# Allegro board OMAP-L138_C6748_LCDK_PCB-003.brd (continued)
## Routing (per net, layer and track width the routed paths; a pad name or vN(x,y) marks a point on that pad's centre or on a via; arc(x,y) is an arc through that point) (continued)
VCC_5VD: length 315.3
  TOP w0.254: 25.15,49.53 25.15,49.53 U16.7 ; U3.4 30.73,74.93 v1(30.48,75.18) 30.23,74.93 U3.5 ; U3.9 v1(26.92,72.87) ; 24.89,49.53 24.65,49.77 U15.1 ; U3.28 v1(33.78,70.87) ; U3.15 v1(26.92,69.87)
  TOP w0.457: v1(30.23,64.26) R13.2 R10.2 R11.2 ; v1(23.37,39.37) 23.69,39.69 DN2.2 ; 24.89,49.53 v1(26.67,49.53) ; v1(32.77,67.06) 33.27,66.55 C7.1 ; DN1.2 21.27,39.69 v1(21.59,39.37)
  LYR3 w0.457: v1(86.36,43.69) 87.12,43.69 88.73,42.08 100.58,42.08 ; 20.57,72.64 7.37,72.64 TP3.1
  LYR3 w1.016: J5.1 67.87,2.74 69.6,1.02 99.57,1.02 100.58,2.03 100.58,89.15 99.57,90.17 73.91,90.17 71.63,87.88 55.88,87.88 53.34,85.34 41.91,85.34 40.13,83.57 40.13,82.8
  LYR4 w0.762: v1(26.67,49.53) 27.94,49.53 ; 27.94,49.53 27.94,61.21 30.23,63.5 v1(30.23,64.26) v1(31.24,64.26) ; 27.94,49.53 27.94,43.94 v1(23.37,39.37) v1(21.59,39.37)
  BOTTOM w0.381: U5.7 v1(22.28,80.72) ; U5.6 v1(22.93,80.72) ; U5.8 v1(21.63,80.72)
  BOTTOM w0.457: 25.91,49.53 25.4,49.53 24.89,50.04 C104.1 ; 25.91,49.53 v1(26.67,49.53) ; 25.91,49.53 C141.1 ; U4.7 34.29,85.09 v1(36.32,83.06) 36.68,82.7 U6.5 ; R26.2 R23.2 v1(20.57,70.36) ; R3.1 33.27,70.36 v1(33.78,70.87) ; R9.1 5.84,76.71 5.59,76.45 5.59,74.42 TP3.1 ; R211.1 v1(86.36,43.69) 86.36,43.94 85.85,44.45 82.8,44.45 82.3,43.94 R210.1 ; v1(20.57,66.55) R22.2 R24.2 ; v1(26.92,69.87) 25.1,69.87 C8.1 ; C18.1 29.97,66.04 30.23,65.79 R13.2 R15.1 v1(31.24,64.26) ; C9.1 25.11,72.87 v1(26.92,72.87) ; C10.1 v1(30.48,75.18) ; U4.14 v1(29.21,80.39) ; R12.2 v1(32.77,74.68) ; v1(21.59,39.37) R121.1 R120.1
VCC_5VD_IN: length 57.9
  TOP w0.305: U2.5 v1(12.95,76.2) ; U2.4 12.18,75.7 12.45,75.44 v1(12.95,75.44)
  TOP w0.457: v1(12.95,73.91) C2.1 14.29,74.68 ; v1(12.95,73.91) C3.1 ; v1(12.95,73.91) v1(12.95,74.68) ; v1(12.95,75.44) v1(12.95,76.2) C1.1 14.29,75.44 ; v1(12.95,75.44) v1(12.95,74.68) ; v1(12.95,75.44) 14.29,75.44 ; 14.29,74.68 v1(12.95,74.68) ; 14.29,74.68 14.29,75.44
  LYR3 w0.762: 22.28,86.49 20.95,85.16 20.95,84.45 TP1.1 17.27,80.77 17.27,78.49 14.99,76.2 v1(12.95,76.2) v1(12.95,75.44) v1(12.95,74.68) v1(12.95,73.91) ; 22.28,86.49 31.88,86.49 ; 22.28,86.49 v1(22.28,87.38) ; 31.88,86.49 v1(33.02,87.63) ; 31.88,86.49 31.88,83.69 v1(30.99,82.8)
  BOTTOM w0.381: U5.2 v1(22.28,87.38) 22.73,87.38 22.93,87.18 U5.3
  BOTTOM w0.457: U4.13 30.48,82.3 v1(30.99,82.8) ; U4.8 35.56,87.38 35.31,87.63 v1(33.02,87.63) 33.02,87.88 32.51,88.39 R21.1
VCC_AIC3106_3V3A: length 3.8
  BOTTOM w0.457: C183.1 v1(18.8,25.65) ; v1(18.8,25.65) C182.1 ; v1(18.8,25.65) v1(18.8,24.89)
VCC_AIC3106_3V3D: length 31.9
  TOP w0.254: 14.49,24.14 v1(14.48,24.13) ; U22.24 17.99,24.98 v1(17.91,24.89) ; v1(13.97,34.29) 14.49,33.77 U22.44
  TOP w0.457: C190.1 v1(13.97,34.29) ; v1(17.91,24.89) v1(17.14,24.13)
  BOTTOM w0.457: 13.46,24.89 C187.1 12.7,25.65 11.94,26.42 11.94,32.26 v1(13.97,34.29) ; 13.46,24.89 v1(13.46,24.13) ; 13.46,24.89 14.48,24.89 ; v1(14.48,24.13) 14.48,23.37 ; v1(14.48,24.13) v1(13.46,24.13) ; v1(14.48,24.13) 14.48,24.89 ; 14.48,23.37 13.46,23.37 ; 14.48,23.37 C188.1 C189.1 13.46,23.37 ; v1(13.46,24.13) 13.46,23.37 ; 17.14,24.89 14.48,24.89 ; 17.14,24.89 v1(17.91,24.89) 17.91,23.43 FB16.1 17.14,23.43 v1(17.14,24.13) 17.14,24.89
VCC_USB0_IN: length 11.7
  TOP w0.457: v1(36.32,84.33) 36.83,84.84 R54.2 ; v1(33.02,84.33) 32.77,84.58 J2.1
  LYR4 w0.457: v1(33.02,84.33) v1(36.32,84.33)
  BOTTOM w0.457: U4.6 v1(33.02,84.33) 34.29,83.06 U4.10
VCC_USB0_IN_K: length 16.7
  BOTTOM w0.381: U5.4 25.19,86.07
  BOTTOM w0.457: 29.21,85.09 U4.3 R25.1 C19.1 ; 29.21,85.09 26.16,85.09 25.19,86.07 ; 29.21,85.09 30.73,85.09 33.02,82.8 U4.11
VDD_ALIVE: length 12
  TOP w0.121: U3.12 27.17,71.37 v1(26.92,71.12) 26.42,71.12 25.53,70.23 25.53,69.72 25.15,69.34 C15.1
  LYR4 w0.133: v1(26.92,71.12) 26.16,70.36 26.16,68.07 25.65,67.56 24.38,67.56 TP8.1
ACTIVITYLED: length 33.6
  TOP w0.121: v1(72.64,73.66) 72.14,73.15 72.14,72.14 72.4,71.87 U23.3
  LYR3 w0.133: v1(72.64,73.66) 72.14,73.15 72.14,72.13 72.64,71.63 96.27,71.63 v1(96.77,71.12)
  BOTTOM w0.121: R188.1 72.39,74.93 72.64,74.68 v1(72.64,73.66) ; R181.1 v1(96.77,71.12)
AES_ADDR/FS: length 2.7
  TOP w0.121: U26.D5 v1(9.91,8.62)
  BOTTOM w0.121: v1(9.91,8.62) 8.87,9.65 R205.2
AES_CLK: length 5
  TOP w0.121: R200.2 R201.2 13.97,12.19 13.7,11.92 U26.E2
AES_DATA: length 4.9
  TOP w0.121: R204.2 R202.2 U26.E3
AIC_BCLK: length 123.5
  TOP w0.121: v1(18.54,35.81) 18.54,34.29 17.49,33.24 U22.38
  LYR3 w0.133: v1(72.64,47.75) 69.34,51.05 34.92,51.05 34.29,50.42 31.88,50.42 28.96,47.5 28.96,40.77 25.53,37.34 23.75,37.34 22.23,35.81 v1(18.54,35.81) ; v1(71.76,45.7) 84.86,45.7 85.28,45.28 85.93,45.28 v1(86.36,45.7)
  BOTTOM w0.121: v1(72.64,47.75) 72.64,46.58 v1(71.76,45.7) R95.2 ; J15.41 97.16,19.05 97.16,23.5 96.52,24.13 95.25,24.13 94.74,24.64 94.74,30.73 93.98,31.5 93.98,38.86 93.22,39.62 89.03,39.62 87.88,40.77 87.88,44.2 86.38,45.7 v1(86.36,45.7)
AIC_MCLK: length 131.5
  TOP w0.121: v1(68.56,44.1) 70.69,46.23 86.61,46.23 88.39,44.45 98.81,44.45 99.57,43.69 99.57,22.1 99.06,21.59 97.16,21.59 J15.39 ; v1(19.05,34.29) 18.29,33.53 18.29,33.52 17.99,33.22 U22.37
  TOP w0.254: U7.A3 v1(68.56,44.1)
  LYR3 w0.133: v1(19.05,34.29) 21.34,34.29 24,36.96 25.78,36.96 29.34,40.51 29.34,47.24 32.13,50.04 34.54,50.04 35.18,50.67 66.93,50.67 v1(68.58,49.02)
  LYR4 w0.121: 68.56,46.1 v1(68.56,44.1)
  LYR4 w0.133: 68.56,46.1 68.56,49 v1(68.58,49.02)
  BOTTOM w0.121: R164.1 20.83,32.51 v1(19.05,34.29)
AIC_MCLK_K: length 2.7
  BOTTOM w0.121: Y5.3 24.13,32.39 24.01,32.51 R164.2
AIC_WCLK: length 120.1
  TOP w0.121: U22.39 16.99,33.25 18.03,34.29 18.03,36.32 v1(18.54,36.83)
  LYR3 w0.133: v1(72.64,48.51) 69.72,51.44 34.67,51.44 34.04,50.8 31.62,50.8 28.57,47.75 28.57,41.02 25.27,37.72 23.5,37.72 22.61,36.83 v1(18.54,36.83) ; v1(85.6,43.69) 84.45,44.83 72.09,44.83 v1(71.76,44.5)
  BOTTOM w0.121: R94.2 v1(71.76,44.5) 73.04,45.78 73.04,48.11 v1(72.64,48.51) ; v1(85.6,43.69) 85.72,43.56 85.72,37.97 87.88,35.81 87.88,35.05 88.39,34.54 88.39,27.18 88.65,26.92 90.04,26.92 91.06,25.91 91.06,22.23 91.69,21.59 94.61,21.59 J15.37
AUDIO_IN_AXR8/ECAP1_APWM2: length 44.1
  TOP w0.254: v1(65.36,43.3) U7.E4
  LYR3 w0.121: v1(65.36,43.3) 65.76,42.9 65.76,42.33 65.99,42.1 68.14,42.1 68.94,42.9 68.96,42.9
  LYR3 w0.133: 68.96,42.9 72.42,42.9 72.9,42.42 81.53,42.42 82.55,41.4 85.6,41.4 86.23,40.77 87.88,40.77 89.03,39.62 96.39,39.62 97.28,38.73 97.28,31.62 98.42,30.48
AUDIO_LEFT: length 3.8
  BOTTOM w0.121: C178.2 40.83,7.11 R156.1 44.29,7.11 J10.6
AUDIO_RIGHT: length 3.8
  BOTTOM w0.121: J10.5 34.45,7.11 R157.1 37.91,7.11 C179.2
AVID/GPIO: length 4.7
  TOP w0.121: U21.36 46.4,23.07 48.26,21.21 TP14.1
AXR0/ECAP0_APWM0/MII_TXD0: length 41.7
  TOP w0.121: v1(62.56,48.9) 63.95,50.29 69.09,50.29 70.48,51.69 70.48,58.17 74.8,62.48 80.77,62.48 82.68,64.39 82.68,70.48 81.29,71.87 U23.22
  BOTTOM w0.121: R90.2 v1(62.56,48.9)
AXR1/MII_TXD1: length 41.6
  TOP w0.121: U23.23 81.3,72.37 83.06,70.61 83.06,64.26 80.9,62.1 74.93,62.1 70.87,58.04 70.87,51.56 69.34,50.04 64.9,50.04 v1(63.76,48.9)
  BOTTOM w0.121: R93.2 v1(63.76,48.9)
AXR2/MII_TXD2: length 41.5
  TOP w0.121: U23.24 81.31,72.87 83.44,70.74 83.44,64.14 81.03,61.72 75.06,61.72 71.25,57.91 71.25,51.44 69.6,49.78 65.85,49.78 v1(64.96,48.9)
  BOTTOM w0.121: R92.2 v1(64.96,48.9)
AXR3/MII_TXD3: length 42.3
  TOP w0.121: v1(66.16,48.9) 66.79,49.53 69.85,49.53 71.63,51.31 71.63,57.78 75.18,61.34 81.15,61.34 83.82,64.01 83.82,70.87 81.53,73.15 79.76,73.15 79.31,73.59 U23.25
  BOTTOM w0.121: R91.2 v1(66.16,48.9)
AXR4/MII_COL: length 43.1
  TOP w0.121: U7.D1 66.69,46.23 68.33,46.23 72.77,50.67 72.77,57.15 v1(74.42,58.8) ; R183.1 v1(80.01,64.77)
  LYR3 w0.133: v1(80.01,64.77) 80.01,66.42 79.88,66.55 73.15,66.55 73.03,66.42 73.03,63.12 73.15,62.99 75.44,62.99 75.56,62.87 75.56,62.36 75.44,62.23 73.15,62.23 73.03,62.1 73.03,58.93 73.15,58.8 v1(74.42,58.8)
  BOTTOM w0.121: R280.2 80.77,65.53 80.64,65.41 80.64,65.02 80.39,64.77 v1(80.01,64.77)
AXR5/MII_TXCLK: length 41.6
  TOP w0.121: v1(69.6,57.91) 69.6,61.09 69.85,61.34 72.64,61.34 74.55,63.25 80.52,63.25 81.92,64.64 81.92,68.71 R182.1
  TOP w0.254: v1(66.16,44.1) U7.D3
  BOTTOM w0.121: v1(69.6,57.91) 69.6,55.88 69.09,55.37 69.09,52.58 68.83,52.32 68.33,52.32 68.07,52.58 68.07,53.59 67.82,53.85 66.93,53.85 66.67,53.59 66.67,46.34 66.56,46.23 66.56,44.46 66.2,44.1 v1(66.16,44.1)
AXR6/MII_TXEN: length 42.3
  TOP w0.121: U23.21 81.28,71.37 82.3,70.36 82.3,64.52 80.64,62.87 74.68,62.87 70.1,58.29 70.1,55.63 v1(69.6,55.12)
  TOP w0.254: v1(66.96,45.7) U7.C1
  BOTTOM w0.121: v1(69.6,55.12) 69.6,50.67 69.34,50.42 68.58,50.42 68.33,50.67 68.33,51.31 68.07,51.56 67.31,51.56 67.06,51.31 67.06,45.8 v1(66.96,45.7)
AXR7/EPWM1TZ0: length 42.2
  TOP w0.254: v1(66.16,44.9) U7.D2
  LYR3 w0.121: 68.96,44.7 68.2,44.7 67.99,44.5 66.56,44.5 v1(66.16,44.9)
  LYR3 w0.133: 68.96,44.7 69.09,44.7 69.85,43.94 71.88,43.94 72.39,44.45 84.2,44.45 84.96,43.69 84.96,43.31 85.85,42.42 87.12,42.42 87.96,41.58 99.01,41.58 99.44,41.15 99.44,36.58 98.42,35.56
AXR13: length 70
  TOP w0.121: U22.40 16.49,33.51 v1(17.27,34.29) R161.1
  TOP w0.254: v1(67.76,44.1) U7.B3
  LYR3 w0.133: v1(17.27,34.29) 17.68,33.88 21.56,33.88 24.26,36.58 26.04,36.58 29.72,40.26 29.72,45.97 30.73,46.99 31.5,46.99 34.16,49.66 34.8,49.66 35.43,50.29 66.55,50.29 v1(67.82,49.02)
  BOTTOM w0.121: v1(67.76,44.1) 67.66,44.1 67.36,44.4 67.36,45.77 67.36,47.54 67.36,47.54 67.36,48.57 v1(67.82,49.02)
AXR14: length 83.6
  TOP w0.121: U22.41 15.99,33.52 16.51,34.04 16.51,36.32 v1(16,36.83)
  TOP w0.254: v1(67.76,43.3) U7.B4
  LYR3 w0.133: v1(72.64,49.28) 70.1,51.82 32,51.82 28.19,48.01 28.19,41.27 25.02,38.1 23.24,38.1 22.48,37.34 16.51,37.34 v1(16,36.83)
  BOTTOM w0.121: v1(72.64,49.28) 73.39,48.53 73.39,45.45 71.44,43.5 70.96,43.5 70.86,43.4 70.85,43.4 70.75,43.3 v1(67.76,43.3)
AXR15/EPWMN0_TZ0/ECAP2_APWM2: length 48.3
  TOP w0.121: 98.42,25.4 97.41,26.42 97.41,41.27 96.65,42.04 89.28,42.04 86.49,44.83 81.03,44.83 80.39,45.47 72.39,45.47 72.14,45.21 70.47,45.21 U7.A4
BRD_RSTN: length 98.2
  TOP w0.121: v1(72.39,78.74) 69.85,81.28 61.72,81.28 60.33,82.68 U1.7 ; v1(69.34,26.92) 73.37,30.95 73.37,32.73 73.98,33.34 U11.6 73.98,35.37 74.68,36.07 79.88,36.07 v1(80.14,36.32)
  TOP w0.254: v1(60.56,34.5) U7.K14
  LYR4 w0.121: v1(60.56,34.5) 61.26,34.5 61.72,34.04 61.72,33.53 61.95,33.3 63.93,33.3 64.16,33.07 64.16,32.73 64.39,32.5 64.73,32.5 64.96,32.27 64.96,31.93 65.19,31.7 65.53,31.7 65.76,31.47 65.76,30.2 65.66,30.1
  LYR4 w0.133: 65.66,30.1 65.66,29.59 68.33,26.92 v1(69.34,26.92) ; v1(80.14,36.32) 82.8,38.99 82.8,44.45 85.85,47.5 85.85,65.28 77.98,73.15 75.44,73.15 73.03,75.56 73.03,78.11 v1(72.39,78.74)
CAM_CLK: length 34.7
  TOP w0.121: U7.W14 53.44,34.9 51.31,32.77 51.31,29.08 47.5,25.27 v1(47.5,23.62) R81.2 ; J16.9 56.13,15.03 v1(56.13,13.46)
  LYR4 w0.133: v1(56.13,13.46) 51.05,18.54 51.05,22.35 49.78,23.62 v1(47.5,23.62)
  BOTTOM w0.121: U27.4 54.29,14.29 55.12,13.46 v1(56.13,13.46)
CPU_DDR_A0: length 8.9
  TOP w0.254: v1(54.96,40.9) U7.U7
  BOTTOM w0.121: v1(54.96,40.9) 54.53,40.9 54.03,41.4 52.02,41.4 51.94,41.48 51.94,41.71 52.02,41.78 53.39,41.78 53.47,41.86 53.47,42.09 53.39,42.16 51.13,42.16 51.05,42.09 51.05,41.91 R230.1
CPU_DDR_A1: length 8.9
  TOP w0.254: v1(55.76,40.9) U7.T7
  BOTTOM w0.121: v1(55.76,40.9) 55.76,41.22 55.68,41.3 54.58,41.3 53.47,42.42 52.04,42.42 51.96,42.49 51.96,42.72 52.04,42.8 52.76,42.8 52.83,42.88 52.83,43.05 52.7,43.18 51.13,43.18 51.05,43.1 51.05,42.93 R231.1
CPU_DDR_A2: length 8.6
  TOP w0.121: U7.W6 52.3,41.3 50.55,43.05 50.55,43.99 50.47,44.07 50.24,44.07 50.16,43.99 50.16,43.26 50.09,43.18 48.34,43.18 48.26,43.1 48.26,42.93 R232.1
CPU_DDR_A3: length 9.1
  TOP w0.121: U7.V6 54.16,41.7 52.28,41.7 50.93,43.05 50.93,44.07 50.42,44.58 50.04,44.58 49.91,44.45 49.91,44.27 49.83,44.2 48.34,44.2 48.26,44.12 48.26,43.94 R233.1
CPU_DDR_A4: length 8.9
  TOP w0.254: v1(54.96,42.5) U7.U5
  BOTTOM w0.121: R234.1 51.05,45.97 51.05,46.15 51.13,46.23 51.87,46.23 51.94,46.3 51.94,46.79 52.02,46.86 52.76,46.86 52.83,46.79 52.83,44.2 54.53,42.5 v1(54.96,42.5)
CPU_DDR_A5: length 9
  TOP w0.121: U7.V5 54.16,42.5 52.62,42.5 52.32,42.8 52.32,43.56 49.66,46.23 48.34,46.23 48.26,46.15 48.26,45.97 R235.1
CPU_DDR_A6: length 9
  TOP w0.121: R236.1 48.26,44.96 48.26,45.14 48.34,45.21 50.29,45.21 51.31,44.2 51.31,43.13 51.38,43.05 51.61,43.05 51.69,43.13 51.69,43.36 51.77,43.43 51.99,43.43 52.07,43.36 52.07,42.42 52.39,42.1 U7.W5
CPU_DDR_A7: length 8.5
  TOP w0.254: v1(54.96,41.7) U7.U6
  BOTTOM w0.121: v1(54.96,41.7) 54.57,41.7 52.83,43.43 52.02,43.43 51.94,43.51 51.94,43.74 52.02,43.81 52.25,43.81 52.32,43.89 52.32,44.88 52.25,44.96 52.02,44.96 51.94,44.88 51.94,44.27 51.87,44.2 51.13,44.2 51.05,44.12 51.05,43.94 R237.1
CPU_DDR_A8: length 8.7
  TOP w0.254: v1(54.96,43.3) U7.U4
  BOTTOM w0.121: R238.1 51.05,48.01 51.05,48.18 51.13,48.26 51.82,48.26 52.7,47.37 53.09,47.37 53.34,47.12 53.34,44.45 54.49,43.3 v1(54.96,43.3)
CPU_DDR_A9: length 9.9
  TOP w0.254: v1(55.76,41.7) U7.T6
  BOTTOM w0.121: R239.1 51.05,44.96 51.05,45.14 51.13,45.21 52.12,45.21 52.2,45.29 52.2,46.15 52.27,46.23 52.5,46.23 52.58,46.15 52.58,44.07 54.55,42.1 55.36,42.1 v1(55.76,41.7)
CPU_DDR_A10: length 8.8
  TOP w0.121: U7.W4 53.66,42.8 52.83,42.8 52.58,43.05 52.58,43.69 50.04,46.23 50.04,47.12 49.91,47.24 48.34,47.24 48.26,47.17 48.26,46.99 R240.1
CPU_DDR_A11: length 8.9
  TOP w0.254: v1(55.76,43.3) U7.T4
  BOTTOM w0.121: R241.1 51.69,48.77 52.83,47.62 53.34,47.62 53.59,47.37 53.59,44.58 54.47,43.7 55.13,43.7 55.53,43.3 v1(55.76,43.3)
CPU_DDR_A12: length 10
  TOP w0.121: U7.V4 54.16,43.3 53.35,43.3 50.29,46.35 50.29,47.62 49.53,48.39 48.34,48.39 48.26,48.31 48.26,48.01 R242.1
CPU_DDR_A13: length 9.4
  TOP w0.254: v1(55.76,42.5) U7.T5
  BOTTOM w0.121: R243.1 51.05,46.99 51.05,47.17 51.13,47.24 52.5,47.24 52.63,47.12 52.96,47.12 53.09,46.99 53.09,44.32 54.51,42.9 55.36,42.9 v1(55.76,42.5)
CPU_DDR_BA0: length 8.7
  TOP w0.254: v1(54.16,40.1) U7.V8
  BOTTOM w0.121: R265.1 48.26,41.4 48.26,40.51 48.39,40.39 48.96,40.39 49.09,40.51 49.09,40.77 49.21,40.89 53.72,40.89 54.16,40.46 v1(54.16,40.1)
CPU_DDR_BA1: length 9
  TOP w0.254: v1(55.76,39.3) U7.T9
  BOTTOM w0.121: R266.1 48.51,38.86 48.77,38.61 55.07,38.61 v1(55.76,39.3)
CPU_DDR_BA2: length 9.8
  TOP w0.254: v1(54.96,40.1) U7.U8
  BOTTOM w0.121: v1(54.96,40.1) 54.9,40.1 53.85,41.15 49.21,41.15 49.09,41.27 49.09,43.05 48.96,43.18 48.64,43.18 48.51,43.05 R267.1
CPU_DDR_CASN: length 9.1
  TOP w0.254: v1(54.96,39.3) U7.U9
  BOTTOM w0.121: R127.1 51.05,39.37 51.05,39.55 51.13,39.62 53.39,39.62 53.47,39.55 53.47,39.32 53.39,39.24 52.02,39.24 51.94,39.17 51.94,38.94 52.02,38.86 54.88,38.86 54.96,38.94 v1(54.96,39.3)
CPU_DDR_CKE: length 9
  TOP w0.121: R130.1 48.26,41.4 48.26,41.22 48.34,41.15 49.04,41.15 49.11,41.22 49.11,42.09 49.19,42.16 49.83,42.16 49.91,42.24 49.91,42.46 50.12,42.67 50.55,42.67 52.32,40.9 54.16,40.9 U7.V7
CPU_DDR_CLKN: length 8.8
  TOP w0.095: R132.1 48.91,40.24 49.75,40.24 49.93,40.42 49.93,41.67 50.23,41.96 50.76,41.96 51.44,41.29 51.44,40.94 51.05,40.56 51.05,40.32 51.13,40.24 51.46,40.24 53.5,40.24 U7.W7
CPU_DDR_CLKP: length 8.8
  TOP w0.095: R131.1 48.85,39.96 49.87,39.96 50.21,40.31 50.21,41.55 50.34,41.68 50.65,41.68 51.16,41.17 51.16,41.06 50.77,40.68 50.77,40.2 51.01,39.96 51.57,39.96 51.57,39.96 53.5,39.96 U7.W8
CPU_DDR_CSN: length 8.8
  TOP w0.121: R126.1 48.39,38.73 48.39,39.04 48.46,39.12 48.94,39.12 49.15,38.91 49.15,38.18 49.23,38.1 49.58,38.1 49.66,38.18 49.66,38.65 49.95,38.94 49.95,39.22 50.02,39.3 54.38,39.3 54.56,39.12 U7.V9
CPU_DDR_DQ0: length 8.7
  TOP w0.254: v1(54.96,33.7) U7.U15
  BOTTOM w0.121: R107.2 51.05,28.7 51.05,28.52 51.13,28.45 51.82,28.45 52.32,28.96 52.32,29.59 53.85,31.11 53.85,33.02 54.53,33.7 v1(54.96,33.7)
CPU_DDR_DQ1: length 8.7
  TOP w0.254: v1(54.96,34.5) U7.U14
  BOTTOM w0.121: v1(54.96,34.5) 54.69,34.5 53.59,33.4 53.59,31.24 52.58,30.23 52.07,30.23 51.94,30.1 51.94,29.59 51.82,29.46 51.13,29.46 51.05,29.54 51.05,29.72 R108.2
CPU_DDR_DQ2: length 10.4
  TOP w0.121: U7.V14 54.16,35.3 53.33,35.3 50.97,32.93 50.97,30.77 49.66,29.46 49.45,29.46 49.02,29.04 49.02,28.96 R109.2
CPU_DDR_DQ3: length 8.6
  TOP w0.254: v1(54.96,35.3) U7.U13
  BOTTOM w0.121: R110.2 51.05,31.75 51.05,31.57 51.13,31.5 51.87,31.5 51.94,31.42 51.94,31.11 52.07,30.99 52.45,30.99 53.09,31.62 53.09,33.91 54.48,35.3 v1(54.96,35.3)
CPU_DDR_DQ4: length 9.8
  TOP w0.121: R111.2 49.02,30.99 50.16,30.99 50.47,31.29 50.47,33.45 53.12,36.1 54.16,36.1 U7.V13
CPU_DDR_DQ5: length 8.7
  TOP w0.121: R112.2 49.66,32.51 49.97,32.83 49.97,33.97 52.9,36.9 54.16,36.9 U7.V12
CPU_DDR_DQ6: length 9.2
  TOP w0.121: R115.2 48.51,31.93 48.59,32 48.94,32 49.15,31.8 49.15,31.57 49.23,31.5 49.91,31.5 50.22,31.81 50.22,33.71 53.01,36.5 U7.W12
CPU_DDR_DQ7: length 8.8
  TOP w0.121: R116.2 48.51,33.1 48.59,33.02 49.04,33.02 49.11,33.1 49.11,34.25 49.4,34.54 50.04,34.54 51.5,36 51.5,37.08 51.71,37.3 U7.W11
CPU_DDR_DQ8: length 9.1
  TOP w0.254: v1(55.76,35.3) U7.T13
  BOTTOM w0.121: R138.2 51.05,30.73 51.05,30.56 51.13,30.48 52.32,30.48 53.34,31.5 53.34,33.66 54.58,34.9 55.36,34.9 v1(55.76,35.3)
CPU_DDR_DQ9: length 9.1
  TOP w0.254: v1(55.76,36.9) U7.T11
  BOTTOM w0.121: R140.2 51.05,33.78 51.05,33.54 51.13,33.46 51.76,33.46 51.94,33.27 51.94,32.84 52.02,32.77 52.52,32.77 52.6,32.84 52.6,34.44 54.66,36.5 55.36,36.5 v1(55.76,36.9)
CPU_DDR_DQ10: length 9.3
  TOP w0.254: v1(55.76,38.5) U7.T10
  BOTTOM w0.121: v1(55.76,38.5) 55.76,38.43 55.68,38.35 52.02,38.35 51.94,38.28 51.94,38.05 52.02,37.97 53.26,37.97 53.34,37.9 53.34,37.67 53.26,37.59 51.13,37.59 51.05,37.67 51.05,37.85 R224.2
CPU_DDR_DQ11: length 9.6
  TOP w0.254: v1(55.76,36.1) U7.T12
  BOTTOM w0.121: v1(55.76,36.1) 55.36,35.7 54.37,35.7 52.83,34.16 52.83,31.88 52.7,31.75 52.07,31.75 51.94,31.88 51.94,32.38 51.82,32.51 51.13,32.51 51.05,32.59 51.05,32.77 R225.2
CPU_DDR_DQ12: length 8.7
  TOP w0.254: v1(54.96,37.7) U7.U10
  BOTTOM w0.121: R226.2 51.05,36.83 51.05,36.65 51.13,36.58 53.26,36.58 53.34,36.65 53.34,36.88 53.26,36.96 52.02,36.96 51.94,37.03 51.94,37.26 52.02,37.34 54.03,37.34 54.1,37.41 54.1,37.62 54.18,37.7 v1(54.96,37.7)
CPU_DDR_DQ13: length 8.8
  TOP w0.121: R227.2 50.16,36.58 50.42,36.83 50.42,38.23 50.69,38.5 54.91,38.5 54.99,38.42 54.99,38.3 54.81,38.12 54.79,38.12 54.77,38.1 U7.V10
CPU_DDR_DQ14: length 8.8
  TOP w0.254: v1(54.96,36.9) U7.U11
  BOTTOM w0.121: R228.2 51.05,34.8 51.05,34.62 51.13,34.54 51.87,34.54 51.94,34.47 51.94,33.73 52.02,33.66 52.25,33.66 52.32,33.73 52.32,34.98 52.4,35.05 52.76,35.05 52.83,35.13 52.83,35.48 52.76,35.56 52.65,35.56 52.58,35.64 52.58,35.86 52.65,35.94 53.59,35.94 54.55,36.9 v1(54.96,36.9)
CPU_DDR_DQ15: length 8.7
  TOP w0.121: R229.2 48.46,35.56 48.39,35.64 48.39,35.99 48.46,36.07 48.94,36.07 49.15,35.86 49.15,35.51 49.23,35.43 49.91,35.43 50.04,35.56 50.04,36.07 50.16,36.2 50.67,36.2 50.8,36.32 50.8,37.85 51.05,38.1 U7.W10
CPU_DDR_DQM0: length 9.2
  TOP w0.121: R136.1 49.05,30 49.05,30.13 49.4,30.48 50.29,30.48 50.72,30.91 50.72,33.19 53.23,35.7 U7.W13
CPU_DDR_DQM1: length 8.6
  TOP w0.121: v1(55.76,37.7) 56.56,37.7 U7.R10
  BOTTOM w0.121: R135.1 51.05,35.81 51.05,35.64 51.13,35.56 52.25,35.56 52.32,35.64 52.32,35.86 52.25,35.94 52.02,35.94 51.94,36.02 51.94,36.25 52.02,36.32 53.52,36.32 54.5,37.3 55.36,37.3 v1(55.76,37.7)
CPU_DDR_DQS0: length 9.6
  TOP w0.254: v1(55.76,34.5) U7.T14
  BOTTOM w0.121: v1(55.76,34.5) 55.36,34.1 55.36,33.52 55.14,33.3 54.64,33.3 54.1,32.77 54.1,30.99 52.58,29.46 52.58,28.7 51.82,27.94 R134.1
CPU_DDR_DQS1: length 8.7
  TOP w0.121: U7.V11 54.16,37.7 51.42,37.7 51.18,37.47 51.18,36.2 50.04,35.05 48.46,35.05 48.39,34.98 48.39,34.62 48.46,34.54 R133.1
CPU_DDR_RASN: length 8.6
  TOP w0.121: U7.W9 50.37,38.9 50.04,38.57 50.04,37.16 49.96,37.08 49.73,37.08 49.66,37.16 49.66,37.64 49.58,37.72 49.23,37.72 49.15,37.64 49.15,37.16 49.07,37.08 48.46,37.08 48.39,37.16 48.39,37.47 R128.1
CPU_DDR_WEN: length 10
  TOP w0.254: v1(55.76,40.1) U7.T8
  BOTTOM w0.121: v1(55.76,40.1) 55.36,39.7 53.8,39.7 53.72,39.78 53.72,40.06 53.64,40.13 52.02,40.13 51.94,40.21 51.94,40.31 52.02,40.39 53.52,40.39 53.59,40.46 53.59,40.56 53.52,40.64 51.13,40.64 51.05,40.56 51.05,40.39 R129.1
CVI_AGND: length 726.1
  TOP w0.254: U17.P9 v1(34.16,44.9) ; v1(77.76,54.9) U18.F7 ; U21.26 45.98,18.07 46.23,17.82 v1(46.23,17.53) 46.23,17.32 45.98,17.07 U21.24 ; 18.26,46.74 U13.46 ; v1(40.56,34.5) U17.B2 ; U21.56 35.35,25.61 v1(35.56,25.4) ; Q6.1 77.33,40.24 v1(77.22,40.13) ; 16.26,46.74 U13.42 ; v1(33.02,24.64) 32.95,24.57 U21.62 ; v1(38.86,28.19) 38.86,27.76 38.85,27.75 U21.49 ; U12.5 18.85,63.45 v1(19.05,63.25) ; U21.6 35.85,14.95 v1(35.81,14.99) ; v2(13.21,27.18) 13.49,26.9 U22.15 ; U17.E3 v1(39.76,36.9) ; U21.27 46,18.57 v1(46.23,18.8) ; U18.K3 v1(81.76,58.9) ; v1(32,75.18) 32,74.55 31.73,74.27 U3.2 ; U21.10 v1(37.85,12.45) ; 56.4,69.09 U9.22 56.4,67.83 v2(55.88,67.31) ; U3.26 33.51,69.87 v1(33.78,69.6) ; U7.L11 v1(60.56,37.7) U7.K11 ; U7.N11 v1(58.16,37.7) U7.P11 ; U22.42 15.49,33.78 v1(16,34.29) ; U7.K1 v1(61.36,44.9) U7.K2 ; U14.45 v1(33.85,61.72) ; U7.J8 v1(62.16,40.1) U7.J7 ; Q5.4 84.98,43.8 84.58,44.2 84.07,44.2 v1(83.57,43.69) ; U7.H1 v1(62.96,44.9) U7.H2 ; U7.N12 v1(58.96,36.9) U7.M11 ; v1(24.13,44.45) 24.89,44.45 25.15,44.71 U16.2 ; U7.H9 v1(62.16,39.3) U7.H8 ; U14.39 v1(36.85,61.72) ; U7.L7 v1(59.76,40.1) U7.M7 ; v1(35.76,40.9) U17.J7 ; U3.7 29.23,74.27 v1(28.32,75.18) ; v1(58.96,33.7) U7.M15 ; v1(26.67,63.25) 26.47,63.45 U24.5 ; U14.1 v1(32.35,51.31) ; v2(83.82,12.7) 84.07,12.45 U8.20 ; v1(60.56,43.3) U7.L3 ; U14.48 v1(32.35,61.72) ; U7.L10 v1(59.76,38.5) U7.M10 ; U25.2 21.34,61.21 21.08,61.47 v1(20.32,61.47) ; v1(59.76,31.3) U7.L18 ; U17.F8 v1(34.96,37.7) ; Q5.1 83.68,40.24 v1(83.57,40.13) ; U7.J11 v1(62.16,37.7) U7.J10 v1(62.16,38.5) U7.J9 ; U14.34 v1(39.35,61.72) ; v1(26.67,53.34) 26.47,53.54 U15.5 ; v1(58.96,32.1) U7.M17 ; U24.4 26.47,60.5 v1(26.67,60.71) ; U21.77 32.46,17.07 C147.2 v1(32.77,16) 32.7,16.07 U21.79 ; v1(68.56,30.5) U7.A19 ; U7.M6 v1(58.96,41.7) U7.N5 ; v1(77.22,43.69) 77.72,44.2 78.23,44.2 78.63,43.8 Q6.4 ; U7.K8 v1(60.56,40.1) U7.K7 ; U22.20 15.99,26.91 v2(16.26,27.18) 16.49,26.94 U22.21 ; U7.K10 v1(60.56,38.5) U7.K9 ; v1(40.56,37.7) U17.F2 ; U3.22 v1(31.23,67.82) ; U21.32 45.71,21.07 v1(46.23,21.59) ; v1(43.85,54.1) U14.24 43.85,51.69 43.72,51.56 42.48,51.56 42.35,51.69 U14.21 ; v1(80.16,52.5) U18.C5 ; v1(35.76,36.9) U17.E7 ; U21.3 34.35,12.64 34.54,12.45 v1(34.8,12.45) ; U14.10 v1(36.85,54.1) ; U17.A7 v1(35.76,33.7) ; v1(29.97,21.57) U21.68 ; U8.26 83.8,13.99 v2(83.82,13.97) 84.3,14.45 U8.24 ; U7.M5 v1(59.76,41.7) U7.L5 ; U21.42 42.35,25.9 42.6,25.65 v1(42.93,25.65) ; U8.4 81.03,12.95 v2(81.28,12.7) ; U17.B8 v1(34.96,34.5) ; U18.K8 v1(76.96,58.9) ; v1(62.96,33.7) U7.H15 ; U17.J3 v1(39.76,40.9) ; U14.28 v1(42.35,61.72) ; U14.15 v1(39.35,54.1) ; U15.4 26.47,50.6 v1(26.67,50.8) ; U12.4 18.85,60.5 v1(19.05,60.71) ; U13.11 22.06,51.78 v1(22.1,51.82) ; U17.H8 v1(34.96,39.3) ; U17.D8 v1(34.96,36.1) ; v2(17.27,27.18) 17.49,26.96 U22.26 ; U8.17 v1(86.08,10.95) ; U14.25 v1(43.85,61.72) ; U21.13 39.35,12.72 39.62,12.45 v1(39.88,12.45) ; U7.L8 v1(60.56,39.3) U7.L9 ; v1(46.23,24.64) 46.16,24.57 U21.39 ; v1(41.36,44.1) U17.N1 ; U14.4 v1(33.85,51.31) ; v1(59.76,45.7) U7.M1 ; v1(58.96,43.3) U7.M4 ; v1(40.56,39.3) U17.H2 ; v1(39.76,33.7) U17.A3 ; v1(40.56,36.1) U17.D2
  TOP w0.305: U2.6 12.18,76.7 12.45,76.96 v1(12.95,76.96) ; U2.2 v1(8.64,76.2)
  TOP w0.457: v1(27.93,15.51) J11.4 v1(23.89,15.51) ; R158.1 v1(11.43,36.83) ; U11.2 v1(74.93,30.48) ; R162.1 v1(15.24,36.83) ; v1(55.71,19.56) J16.8 ; Q2.2 v1(16.26,69.92) ; C15.2 C16.1 v1(22.86,68.33) ; 16.19,75.44 C1.2 v1(17.53,76.2) 17.53,75.44 ; 16.19,75.44 17.53,75.44 ; 16.19,75.44 16.19,74.68 ; R17.1 R19.1 v1(22.86,71.37) ; R16.1 R7.2 C7.2 ; U26.C4 v1(12.7,7.62) U26.C2 ; R186.2 v1(73.66,77.47) ; Q4.2 v1(11.94,69.92) ; U28.2 13.72,61.47 v1(14.22,61.98) ; C207.1 v1(10.16,14.99) ; R161.2 v1(17.27,36.83) ; C82.2 v1(57.4,86.36) ; 17.53,74.68 16.19,74.68 ; 17.53,74.68 v1(17.53,73.91) C2.2 16.19,74.68 ; 17.53,74.68 17.53,75.44 ; C180.2 22.61,28.96 22.35,29.21 v1(20.57,29.21) ; v1(64.71,19.56) J16.26 ; v1(56.71,19.56) J16.10 ; 16.26,46.74 16.51,46.99 v2(16.51,48.26) ; J2.5 v1(28.25,83.06) ; R67.1 v1(78.74,33.02) ; R66.1 v1(80.01,33.02) ; C48.1 v1(62.23,74.68) ; C190.2 v1(13.97,36.83) ; C83.2 39.37,86.11 39.62,86.36 v1(41.15,86.36) R52.2 ; 18.26,46.74 17.78,47.22 v2(17.78,48.26) ; DN1.1 19.75,41.59 19.05,40.89 v1(19.05,39.37) ; v1(66.16,27.3) 65.15,26.29 C69.2 66.36,25.08 C66.2 ; v1(62.23,86.36) 63.18,86.36 FB5.2 63.82,86.36 v1(64.77,86.36) ; D3.1 v1(7.37,76.95) ; C47.2 57.15,72.9 ; C7.2 v1(33.27,64.26) ; C7.2 v1(34.29,65.02) ; U26.A3 v1(12.7,4.83) ; 10.29,73.91 v1(9.4,73.91) ; v1(86.36,4.57) 87,4.57 87.32,4.9 J3.5 ; R40.2 v1(63.5,63.5) ; C186.2 C181.2 v1(20.57,31.24) ; R39.2 v1(63.5,67.56) ; C49.1 v1(59.69,74.68) ; Y1.1 v1(55.37,76.07) ; U1.3 v1(61.59,80.01) ; v1(54.71,19.56) J16.6 ; Q3.2 v1(11.94,66.11) ; DN2.1 23.69,41.59 v1(23.37,41.91) ; Q1.2 v1(16.26,66.11) ; J16.25 v1(64.21,13.46) ; R61.2 v1(78.74,24.13) ; C4.2 v1(57.4,82.55) ; v1(71.12,71.12) 70.36,71.12 ; C201.2 v1(72.39,77.47) ; R159.1 v1(12.7,36.83) ; C81.2 v1(54.1,82.87) ; v1(62.23,6.86) 62.23,8.02 J9.3 61.21,8.02 v1(61.21,6.86) v1(62.23,6.86) ; v1(49.53,6.86) 49.53,8.02 J9.4 48.51,8.02 v1(48.51,6.86) v1(49.53,6.86) ; C191.2 14.48,20.64 v1(14.48,19.81) v1(13.46,19.81) 13.46,20.64 C191.2 ; v1(19.56,19.81) 19.56,20.64 C184.2 20.57,20.64 v1(20.57,19.81) v1(19.56,19.81) ; 40.2,71.88 FB1.1 40.2,72.9 v1(40.89,72.9) v1(40.89,71.88) 40.2,71.88
  TOP w1.016: J10.4 34.35,2.01 J11.1
  LYR2_GND w0.838: 48.98,87 J7.1 ; J7.1 49.82,86.16 ; J7.1 49.82,87.83 ; 55.37,0.73 J9.1 ; J9.1 57.16,2.52 ; J9.1 55.37,4.32 ; J9.1 53.58,2.52 ; 18.59,88.9 JP1.1 ; JP1.1 19.68,87.81 ; JP1.1 19.68,89.99 ; JP1.1 20.78,88.9 ; 88.57,12.7 J14.45 ; J14.45 89.53,11.73 ; J14.45 89.53,13.67 ; J14.45 90.5,12.7 ; J15.43 95.89,16.21 ; J15.43 94.92,15.24 ; J15.43 95.89,14.27 ; J15.43 96.85,15.24 ; 4.37,56.26 J8.17 ; J8.17 7.32,56.26 ; J8.17 5.84,54.79 ; J8.17 5.84,57.73 ; 11.67,86 J1.3 ; J1.3 13.72,83.96 ; J1.3 13.72,88.05 ; J1.3 15.76,86 ; J13.11 93.42,73.28 ; J13.11 91.49,73.28 ; J13.11 92.46,74.24 ; J13.11 92.46,72.31 ; 47.28,79.5 S1.4 ; S1.4 47.28,81.94 ; S1.4 46.06,80.72 ; S1.4 48.5,80.72 ; 83.82,26.97 J6.8 ; J6.8 83.82,28.91 ; J6.8 82.85,27.94 ; J6.8 84.79,27.94 ; 42.2,86.16 J7.7 ; J7.7 43.04,87 ; J7.7 41.36,87 ; J7.7 42.2,87.83 ; 98.42,22.86 99.39,22.86 ; 98.42,22.86 98.42,23.83 ; 98.42,22.86 97.46,22.86 ; 98.42,22.86 98.42,21.89 ; 5.03,70.23 P1.19 4.32,70.94 ; 89.27,78.11 J13.5 ; J13.5 91.07,78.11 ; J13.5 90.17,77.2 ; J13.5 90.17,79.01 ; 7.49,70.94 P2.20 6.78,70.23 ; J6.4 84.79,22.86 ; J6.4 83.82,23.83 ; J6.4 82.85,22.86 ; J6.4 83.82,21.89 ; 91.11,12.7 J14.46 ; J14.46 93.04,12.7 ; J14.46 92.08,11.73 ; J14.46 92.08,13.67 ; TP6.1 3.81,74.57 ; TP6.1 3.81,72.75 ; TP6.1 2.9,73.66 ; TP6.1 4.72,73.66 ; 5.84,25.53 5.84,27 ; 5.84,25.53 5.84,24.05 ; 5.84,25.53 7.32,25.53 ; 5.84,25.53 4.37,25.53 ; 88.9,80.64 88.9,81.55 ; 88.9,80.64 89.8,80.64 ; 88.9,80.64 88.9,79.74 ; 88.9,80.64 88,80.64 ; 43.09,2.03 J10.1 ; J10.1 44.37,3.32 ; J10.1 44.37,0.75 ; J10.1 45.65,2.03 ; 82.85,30.48 J6.10 ; J6.10 83.82,31.45 ; J6.10 84.79,30.48 ; J6.10 83.82,29.51 ; 98.42,38.1 99.39,38.1 ; 98.42,38.1 98.42,39.07 ; 98.42,38.1 97.46,38.1 ; 98.42,38.1 98.42,37.13 ; 98.42,32.05 98.42,33.02 ; 98.42,33.02 99.39,33.02 ; 98.42,33.02 98.42,33.99 ; 98.42,33.02 97.46,33.02 ; J8.7 4.31,37.85 ; J5.4 75.9,8.89 ; J5.4 73.84,8.89 ; J5.4 74.87,7.86 ; J5.4 74.87,9.92 ; 97.46,27.94 98.42,27.94 ; 98.42,27.94 98.42,26.97 ; 98.42,27.94 99.39,27.94 ; 98.42,27.94 98.42,28.91 ; J14.19 90.5,45.72 ; J14.19 88.57,45.72 ; J14.19 89.53,46.69 ; J14.19 89.53,44.75 ; 33.09,2.03 J10.4 ; J10.4 35.65,2.03 ; J10.4 34.37,3.32 ; J10.4 34.37,0.75 ; 1.26,35.56 J8.6 2.03,34.78 ; 94.92,25.4 J15.35 ; J15.35 96.85,25.4 ; J15.35 95.89,24.43 ; J15.35 95.89,26.37 ; 3.05,70.94 P1.20 2.34,70.23 ; 48.37,70.71 BH1.2 ; BH1.2 49.53,71.87 ; BH1.2 50.69,70.71 ; BH1.2 49.53,69.55 ; J1.2 10.96,82.75 ; J1.2 8.92,84.8 ; J1.2 8.92,80.71 ; 98.42,43.18 98.42,44.15 ; 98.42,43.18 99.39,43.18 ; 98.42,43.18 97.46,43.18 ; 98.42,43.18 98.42,42.21 ; J14.20 93.04,45.72 ; J14.20 91.11,45.72 ; J14.20 92.08,44.75 ; J14.20 92.08,46.69 ; 47.28,73 S1.3 ; S1.3 46.06,74.22 ; S1.3 48.5,74.22 ; S1.3 47.28,75.44 ; 98.42,17.78 99.39,17.78 ; 98.42,17.78 98.42,18.75 ; 98.42,17.78 97.46,17.78 ; 98.42,17.78 98.42,16.81 ; 8.76,70.94 P2.19 9.47,70.23 ; 83.82,32.05 J6.12 ; J6.12 82.85,33.02 ; J6.12 84.79,33.02 ; J6.12 83.82,33.99 ; 70.21,24.13 TP7.1 ; TP7.1 72.03,24.13 ; TP7.1 71.12,23.22 ; TP7.1 71.12,25.04 ; 1.26,40.13 J8.8 ; 1.26,46.23 J8.5 2.03,47 ; J7.4 46.85,87 ; J7.4 46.01,87.83 ; J7.4 46.01,86.16 ; J7.4 45.17,87 ; 1.26,44.7 J8.10
  BOTTOM w0.381: C40.2 v1(61.36,44.9) ; C78.2 v1(62.16,39.3) ; v1(62.16,39.3) v1(62.16,40.1) ; v1(62.16,39.3) v1(62.16,38.5) v1(62.16,37.7) C62.2 ; v1(62.16,40.1) 61.36,40.1 ; v1(62.16,40.1) 62.57,40.1 62.85,40.39 C57.2 ; 61.36,40.1 v1(60.56,40.1) ; 61.36,40.1 C74.2 ; 61.36,40.1 C75.2 60.67,39.41 v1(60.56,39.3) ; v1(59.76,40.1) 59.87,40.21 C79.2 59.87,41.59 v1(59.76,41.7) ; v1(59.76,40.1) 59.87,39.99 C38.2 59.87,38.61 v1(59.76,38.5) 59.87,38.39 C39.2 v1(60.56,37.7) v1(60.56,38.5) v1(60.56,39.3) ; v1(59.76,40.1) v1(60.56,40.1) ; v1(62.96,33.7) 62.85,33.81 C61.2 ; C41.2 61.25,33.7 v1(60.56,33.7) 59.87,34.39 C55.2 ; C35.2 56.56,40.79 v1(56.56,40.1) 56.56,39.41 C37.2 ; C51.2 56.56,42.61 v1(56.56,43.3) ; C65.2 56.56,34.61 v1(56.56,35.3) 56.56,35.99 C36.2 ; v1(59.76,41.7) 59.87,41.81 C67.2 ; v1(59.76,41.7) v1(58.96,41.7) ; C52.2 56.56,37.81 v1(56.56,38.51) ; v1(64.56,42.5) C58.2 ; v1(60.56,35.3) 61.25,35.99 C77.2 62.05,35.99 v1(62.16,36.1) C44.2 ; v1(60.56,40.1) v1(60.56,39.3) ; v1(58.96,36.9) 58.85,36.79 C53.2 ; C59.2 58.85,43.41 v1(58.96,43.3) ; U5.1 21.63,84.92 v3(21.97,84.58)
  BOTTOM w0.457: C148.2 v1(34.8,12.45) ; C170.2 55.73,45.95 56.58,46.8 56.58,47.94 56.85,48.21 C68.2 v1(57.36,48.9) ; C202.1 v1(71.12,71.12) C203.1 ; v1(77.22,43.69) R101.1 77.72,42.42 77.98,42.16 77.98,41.66 78.23,41.4 R102.1 ; C100.1 40.01,52.2 39.35,52.85 v1(39.35,54.1) ; R37.2 55.37,64.26 v2(55.88,64.77) ; C31.2 56.64,67.82 v2(57.15,67.31) ; C161.2 v1(33.78,14.99) ; v1(13.46,19.81) C189.2 C188.2 v1(14.48,19.81) ; C159.2 30.99,13.21 30.73,13.46 v1(30.73,14.99) ; R78.1 v1(55.88,58.93) ; C144.2 74.42,69.34 v2(74.93,69.85) ; U6.3 40.19,86.17 40.39,86.36 v1(41.15,86.36) ; C130.2 v1(44.16,38.5) ; R274.1 31.05,18.86 30.73,19.18 30.73,21.34 ; R155.1 v1(41.91,11.43) ; 40.64,60.83 v1(40.64,61.72) ; 30.73,21.34 C154.2 ; 30.73,21.34 30.5,21.57 v1(29.97,21.57) ; C133.2 v1(44.16,35.3) ; v1(71.76,37.7) C60.2 C56.2 v1(71.76,36.5) ; U4.5 v1(31.75,87.63) 31.36,87.63 31.11,87.88 31.11,89.41 ; v1(29.21,64.26) C18.2 C17.2 ; v2(57.15,64.77) 57.66,64.26 C32.2 ; C157.2 C147.2 v1(32.77,16) ; C42.2 R195.1 R197.1 v1(51.82,20.32) ; v2(83.82,11.43) 83.31,10.92 C21.2 ; v1(91.44,86.87) R180.1 v1(87.63,86.87) ; C20.2 80.52,13.46 v2(81.28,12.7) ; C127.2 v1(31.36,33.7) ; C141.2 C118.2 24.89,45.21 v1(24.13,44.45) ; C24.2 85.09,5.08 85.6,4.57 v1(86.36,4.57) v1(88.9,4.57) 89.41,4.57 89.66,4.83 C22.2 ; v1(41.91,14.99) C168.2 C167.2 ; R153.1 v1(36.83,11.43) ; C164.2 v1(35.81,14.99) ; R84.1 v1(44.7,57.91) ; R85.1 v1(38.61,57.91) ; C206.1 22.1,62.48 21.08,61.47 ; R273.2 v1(51.75,6.99) ; v1(9.91,5.59) 9.65,5.84 D8.1 ; v1(33.78,74.68) 33.91,74.8 33.91,76.14 C11.2 34.67,76.14 34.67,74.8 v1(34.8,74.68) ; v1(33.78,74.68) v1(34.8,74.68) ; v1(33.78,74.68) R14.1 R8.2 v1(34.8,74.68) ; 21.08,61.47 C210.2 ; 21.08,61.47 v1(20.32,61.47) ; R199.2 64.52,17.53 64.26,17.78 64.26,19.11 v1(64.71,19.56) ; v1(26.67,53.34) C106.1 ; C45.2 55.37,24.07 v1(55.37,22.86) ; C99.1 36.32,52.2 36.85,52.73 v1(36.85,54.1) ; v2(14.22,27.18) 14.48,26.92 C187.2 ; C50.2 v1(63.76,27.3) ; C8.2 23.18,68.64 v1(22.86,68.33) ; C131.2 v1(44.16,47.7) ; Y5.2 20.83,30.48 20.57,30.73 v1(20.57,31.24) ; R42.2 v1(59.69,58.93) ; v1(22.1,53.85) C103.1 R114.2 R113.2 ; C169.2 45.98,17.78 46.23,17.53 v1(46.23,17.53) ; C94.2 v1(19.05,60.71) ; R255.1 v1(66.04,58.93) ; v1(35.56,25.4) C152.2 ; C28.2 58.93,65.28 v2(58.42,64.77) ; C171.2 47.82,29.97 v1(46.74,29.97) ; v1(46.23,18.8) 45.47,18.8 44.96,19.3 C155.2 R143.1 ; C76.2 v1(71.76,30.5) ; v2(55.88,67.31) 55.37,66.8 R38.2 ; R118.1 v1(10.16,46.23) ; v1(62.23,74.68) 61.47,73.91 C29.2 ; C139.2 v1(79.36,59.7) ; R82.1 v1(42.67,57.91) ; R77.1 v1(53.34,58.93) ; C194.2 v1(93.98,84.58) ; R157.2 v1(36.32,4.32) ; C63.2 v1(71.76,47.7) ; R253.1 v1(60.96,58.93) ; 31.11,89.41 C19.2 R25.2 ; 31.11,89.41 R21.2 ; R213.2 v1(85.09,40.13) ; v1(53.72,69.34) 54.61,70.23 C33.2 ; C158.2 v1(38.86,12.45) ; C149.2 v1(31.75,28.19) ; C174.1 v1(37.85,11.43) ; C177.1 v1(40.89,11.43) ; v2(77.47,69.85) 77.79,70.17 C199.2 ; v2(58.42,67.31) 58.93,66.8 C27.2 ; C126.2 v1(31.36,35.3) ; C145.2 v1(84.33,56.5) ; v1(64.21,13.46) 64.21,15.19 64.52,15.49 R198.2 ; C209.1 v1(6.35,10.92) ; R170.2 74.04,65.53 74.3,65.28 74.3,64.39 74.68,64.01 v1(74.93,64.01) ; J4.6 68.77,88.08 67.69,87 v1(67.69,85.6) ; v2(17.78,48.26) C97.1 R122.2 ; C198.2 v1(90.17,84.58) ; D1.1 8.89,75.25 8.64,75.5 v1(8.64,76.2) ; C115.1 v1(16.51,41.91) ; C121.2 v1(31.36,40.9) ; R76.1 v1(50.8,58.93) ; C165.2 37.85,12.45 v1(37.85,12.45) ; C134.2 v1(44.16,33.7) ; C200.2 v1(77.47,77.47) ; C86.2 v1(57.15,22.86) ; C197.2 v1(85.09,84.58) ; C143.2 25.4,19.81 v1(24.64,19.05) ; C64.2 v1(59.76,48.9) ; v2(83.82,12.7) 84.33,13.21 C23.2 ; R223.2 v1(97.28,5.08) ; C163.2 v1(53.34,6.86) ; C142.2 v1(28.7,24.64) ; C43.2 v1(54.16,29.72) ; v1(35.76,36.9) 37.76,36.9 38.27,36.39 C135.2 ; v1(22.86,71.37) 23.18,71.69 C9.2 ; C129.2 v1(44.16,40.9) ; C6.2 v1(34.29,65.02) ; 35.56,60.83 36.45,60.83 36.83,61.21 36.83,61.7 v1(36.85,61.72) ; C185.2 v1(15.49,24.13) ; C208.1 v1(19.05,4.57) ; v2(76.2,69.85) 76.71,69.34 C193.2 ; C128.2 v1(44.16,45.7) ; C132.2 v1(44.16,36.9) ; C49.1 v1(59.69,74.68) ; C160.2 v1(32.77,14.99) ; R196.1 R33.2 v1(49.53,22.86) ; C123.2 v1(31.36,31.7) ; Y3.2 60.33,25.62 60.33,26.42 60.96,27.05 v1(60.96,27.3) 61.12,27.3 61.37,27.55 R264.2 C25.2 C54.2 v1(58.96,27.3) ; C109.1 v1(8.89,41.91) ; C183.2 v2(16.26,27.18) ; C217.2 v1(14.22,61.98) C216.1 ; C120.2 v1(31.36,43.3) ; v1(56.56,27.3) C70.2 C73.2 ; v1(46.23,24.64) C151.2 R149.1 ; C71.2 v1(66.16,27.3) ; C153.2 v1(42.93,25.65) ; R222.2 v1(4.57,22.1) ; R256.1 v1(68.58,58.93) ; C215.2 v1(49.78,15.49) ; C196.2 v1(86.36,84.58) ; C205.1 v1(26.67,63.25) ; R119.1 v2(16.51,48.26) ; C146.2 v1(34.29,21.59) ; R79.1 v1(58.42,55.12) ; v1(35.76,40.9) R124.2 C136.1 ; R125.2 v1(31.36,42.1) ; v2(15.24,48.26) C98.2 R117.2 C116.1 ; C211.1 v1(19.05,9.65) ; C124.2 v1(31.36,47.7) ; C95.1 v1(19.05,63.25) ; C72.2 v1(61.36,48.9) ; C204.2 v1(26.67,60.71) ; C26.2 v1(54.61,57.91) ; C150.2 39.37,27.94 39.12,28.19 v1(38.86,28.19) ; C111.1 v1(15.24,39.37) ; C104.2 v1(26.67,50.8) ; C80.2 v1(71.76,28.5) ; C122.2 v1(31.36,38.5) ; C10.2 v1(30.48,79.5) ; R83.1 v1(40.64,57.91) ; C138.2 v1(74.42,57.3) ; R254.1 v1(63.5,58.93) ; C108.1 v1(11.43,39.37) ; v1(19.05,5.84) C213.1 R207.2 ; C137.2 v1(92.71,84.58) ; C96.1 20.83,51.18 21.46,51.82 v1(22.1,51.82) ; C112.1 v1(12.7,41.91) ; v1(54.71,19.56) 54.29,19.14 U27.3 ; C114.1 v1(19.05,39.37) ; U4.1 v1(26.67,87.63) ; C125.2 v1(31.36,36.9) ; C140.2 v1(84.33,54.1) ; C166.2 v1(39.88,12.45) ; C212.1 v1(19.05,10.92) ; v1(33.02,24.64) R145.1 ; C156.2 v1(41.91,21.59) ; R212.2 v1(83.57,43.69) ; R156.2 v1(42.42,4.32) ; J4.9 v1(67.27,80.01) ; C201.2 v1(72.39,77.47) ; C182.2 v2(17.27,28.19) ; C214.1 v1(6.35,4.57) ; v1(28.32,75.18) v1(27.56,75.18) 27.56,76.14 C13.2 28.32,76.14 v1(28.32,75.18)
  BOTTOM w0.889: C13.2 C14.2 ; C5.2 C6.2 ; C12.2 C11.2
  vias: v1(24.64,33.02) v1(28.7,33.02) v1(28.7,19.05) v1(66.8,74.42) v1(66.8,67.82) v2(13.21,31.24) v2(13.21,30.23) v2(13.21,29.21) v2(13.21,28.19) v2(14.22,31.24) v2(14.22,30.23) v2(14.22,29.21) v2(14.22,28.19) v2(15.24,50.8) v2(15.24,49.53) v2(15.24,31.24) v2(15.24,30.23) v2(15.24,29.21) v2(15.24,28.19) v2(15.24,27.18) v2(16.26,31.24) v2(16.26,30.23) v2(16.26,29.21) v2(16.26,28.19) v2(16.51,50.8) v2(16.51,49.53) v2(17.27,31.24) v2(17.27,30.23) v2(17.27,29.21) v2(17.78,50.8) v2(17.78,49.53) v2(35.56,22.86) v2(35.56,21.59) v2(35.56,20.32) v2(35.56,19.05) v2(35.56,17.78) v2(36.83,22.86) v2(36.83,21.59) v2(36.83,20.32) v2(36.83,19.05) v2(36.83,17.78) v2(38.1,22.86) v2(38.1,21.59) v2(38.1,20.32) v2(38.1,19.05) v2(38.1,17.78) v2(39.37,22.86) v2(39.37,21.59) v2(39.37,20.32) v2(39.37,19.05) v2(39.37,17.78) v2(40.64,22.86) v2(40.64,21.59) v2(40.64,20.32) v2(40.64,19.05) v2(40.64,17.78) v2(55.88,66.04) v2(57.15,66.04) v2(58.42,66.04) v2(74.93,72.39) v2(74.93,71.12) v2(76.2,72.39) v2(76.2,71.12) v2(77.47,72.39) v2(77.47,71.12) v2(81.28,13.97) v2(81.28,11.43) v2(82.55,13.97) v2(82.55,12.7) v2(82.55,11.43) v3(21.97,83.31) v3(22.61,83.95) v3(23.24,84.58) v3(23.24,83.31)
CVIDEO_DIN0: length 48.6
  TOP w0.121: v1(63.71,19.56) J16.24 ; U21.52 37.35,25.9 v1(37.85,25.4) ; v1(51.82,23.62) 51.82,25.4 53.5,27.08 53.5,30.64 U7.W19
  LYR3 w0.133: v1(63.71,19.56) 63.2,19.05 62.48,19.05 62.23,19.3 62.23,19.81 61.98,20.07 61.21,20.07 61.09,20.19 61.09,20.45 60.96,20.57 59.18,20.57 59.05,20.7 59.05,20.95 59.18,21.08 60.33,21.08 60.45,21.21 60.45,22.48 60.58,22.61 61.21,22.61 61.34,22.73 61.34,23.5 61.21,23.62 v1(51.82,23.62) 51.31,23.11 50.8,23.11 49.78,24.13 43.81,24.13 42.04,25.91 38.35,25.91 v1(37.85,25.4)
  BOTTOM w0.121: R244.2 63.25,19.09 v1(63.71,19.56)
CVIDEO_DIN1: length 50.1
  TOP w0.121: U7.W18 53.25,31.19 53.25,27.34 51.56,25.65 51.56,24.13 v1(51.05,23.62) ; U21.51 37.85,26.92 v1(37.85,28.19) ; J16.23 v1(63.21,13.5)
  LYR3 w0.133: v1(37.85,28.19) 39.88,26.16 45.47,26.16 46.23,25.4 47.24,25.4 48.01,24.64 50.04,24.64 v1(51.05,23.62) 51.56,24.13 61.32,24.13 61.7,23.75 61.7,20.6 v1(61.72,20.57)
  LYR4 w0.133: v1(63.21,13.5) 62.74,13.97 62.74,17.78 62.23,18.29 62.23,20.07 v1(61.72,20.57)
  BOTTOM w0.121: R245.2 63.21,14.44 v1(63.21,13.5)
CVIDEO_DIN2: length 50.3
  TOP w0.121: v1(39.88,28.19) 39.37,28.7 38.73,28.7 38.35,28.32 U21.50 ; U7.W17 53,31.74 53,27.6 51.05,25.65 51.05,24.46 51.02,24.42 v1(51.02,24.38) ; v1(62.71,19.56) J16.22
  LYR3 w0.133: v1(62.71,19.56) 62.71,21.46 62.84,21.59 65.28,21.59 65.41,21.72 65.41,22.48 65.28,22.61 62.84,22.61 62.71,22.73 62.71,24.14 62.46,24.38 v1(51.02,24.38) 50.41,24.99 48.16,24.99 47.5,25.65 46.48,25.65 45.72,26.42 40.39,26.42 39.88,26.92 v1(39.88,28.19)
  BOTTOM w0.121: v1(62.71,19.56) 62.23,19.08 R246.2
CVIDEO_DIN3: length 49.7
  TOP w0.121: U7.V17 54.16,32.9 53.48,32.9 52.75,32.17 52.75,27.86 50.55,25.65 50.55,23.37 51.05,22.86 51.05,21.08 v1(50.29,20.32) ; U21.47 39.85,25.43 v1(39.88,25.4) ; J16.21 v1(62.21,13.46)
  LYR3 w0.133: v1(62.21,13.46) 61.19,14.48 52.83,14.48 v1(49.78,17.53) ; v1(39.88,25.4) 41.91,23.37 43.05,23.37 44.07,22.35 48.77,22.35 49.78,21.34 49.78,20.83 v1(50.29,20.32)
  LYR4 w0.133: v1(49.78,17.53) 50.29,18.03 v1(50.29,20.32)
  BOTTOM w0.121: R247.2 62.21,14.46 v1(62.21,13.46)
CVIDEO_DIN4: length 48.1
  TOP w0.121: U21.46 40.39,26.88 40.39,25.78 v1(40.77,25.4) ; v1(50.29,21.09) 50.8,21.6 50.8,22.61 50.29,23.11 50.29,25.91 52.5,28.12 52.5,32.27 53.53,33.3 U7.W16 ; v1(61.71,19.56) J16.20
  LYR3 w0.133: v1(40.77,25.4) 40.77,25.02 41.66,24.13 42.8,24.13 44.32,22.61 49.03,22.61 50.29,21.34 v1(50.29,21.09) 51.18,21.09 51.31,21.22 51.31,21.46 51.44,21.59 53.98,21.59 54.1,21.46 54.1,20.95 53.98,20.83 52.7,20.83 52.58,20.7 52.58,18.92 52.7,18.8 60.95,18.8 v1(61.71,19.56)
  BOTTOM w0.121: R248.2 61.21,19.06 v1(61.71,19.56)
CVIDEO_DIN5: length 50.8
  TOP w0.121: v1(41.4,29.21) 40.85,28.66 U21.45 ; J16.19 v1(61.21,13.46)
  TOP w0.254: v1(57.36,35.3) U7.R14
  LYR3 w0.133: v1(41.4,29.21) 41.91,28.7 43.18,28.7 44.96,26.92 46.23,26.92 46.74,26.42 55.5,26.42 55.98,26.89 56.74,26.89 57.55,27.7 59.8,27.7 v1(60.2,27.3)
  LYR4 w0.121: v1(57.36,35.3) 57.36,34.59 57.85,34.1 58.33,34.1 58.56,33.87 58.56,33.53 58.56,32.66 58.72,32.5 59.13,32.5 59.36,32.27 59.36,30.3 59.56,30.1
  LYR4 w0.133: 59.56,30.1 60.2,29.46 v1(60.2,27.3) 60.45,27.05 60.45,21.97 61.21,21.21 61.21,18.29 61.72,17.78 61.72,13.97 v1(61.21,13.46)
  BOTTOM w0.121: v1(61.21,13.46) 61.21,14.47 R249.2
CVIDEO_DIN6: length 47.8
  TOP w0.121: U21.44 41.35,25.71 v1(41.66,25.4) ; v1(60.71,19.56) J16.18 ; v1(50.29,22.1) 50.04,22.35 50.04,26.16 52.26,28.38 52.26,32.38 53.58,33.7 54.16,33.7 U7.V16
  LYR3 w0.133: v1(41.66,25.4) 42.04,25.4 44.32,23.11 48.51,23.11 48.77,23.37 49.78,23.37 50.29,22.86 v1(50.29,22.1) 52.45,22.1 52.58,22.23 52.58,23.24 52.7,23.37 60.07,23.37 60.2,23.24 60.2,22.99 60.07,22.86 58.67,22.86 58.55,22.73 58.55,20.32 58.67,20.19 60.58,20.19 60.71,20.07 v1(60.71,19.56)
  BOTTOM w0.121: R250.2 60.2,19.05 v1(60.71,19.56)
CVIDEO_DIN7: length 48.1
  TOP w0.121: v1(42.16,29.21) 42.1,29.21 41.85,28.96 U21.43 ; v1(55.37,27.18) 54.86,27.69 54.86,30.23 54.96,30.32 54.96,31.3 U7.U18 ; v1(59.44,13.47) 59.82,13.47 60.21,13.87 J16.17
  LYR3 w0.133: v1(42.16,29.21) 43.05,29.21 45.09,27.18 46.35,27.18 46.86,26.67 54.86,26.67 v1(55.37,27.18)
  LYR4 w0.133: v1(55.37,27.18) 55.37,23.87 57.15,22.09 57.15,17.14 57.02,17.02 56.52,17.02 56.39,17.14 56.39,18.92 56.26,19.05 55.85,19.05 55.73,18.92 55.73,15.52 58.27,12.97 58.94,12.97 v1(59.44,13.47)
  BOTTOM w0.121: R251.2 60.2,13.84 59.83,13.47 v1(59.44,13.47)
CVIDEO_DIN8: length 15.9
  TOP w0.121: J16.16 59.71,19.43 59.94,19.66 v1(59.94,22.1)
  TOP w0.254: v1(58.16,32.1) U7.P17
  LYR4 w0.121: 57.99,30.1 57.76,30.33 57.76,30.67 57.76,31.7 v1(58.16,32.1)
  LYR4 w0.133: v1(59.94,22.1) 59.94,26.69 59.56,27.07 59.56,28.32 58.42,29.46 58.42,29.67 57.99,30.1
CVIDEO_DIN9: length 21.7
  TOP w0.121: v1(58.42,16.51) 58.93,16.51 59.21,16.23 J16.15
  TOP w0.254: v1(56.56,33.7) U7.R15
  LYR4 w0.121: 55.88,30.1 55.88,31.24 56.34,31.7 56.73,31.7 56.96,31.93 56.96,33.34 56.6,33.7 v1(56.56,33.7)
  LYR4 w0.133: 55.88,30.1 55.88,29.08 56.13,28.83 56.13,25.65 58.04,23.75 58.04,16.89 v1(58.42,16.51)
CVIDEO_DIN10: length 14.1
  TOP w0.121: J16.14 58.71,19.47 v1(58.8,19.56)
  TOP w0.254: v1(56.56,30.5) U7.R19
  LYR4 w0.121: 56.56,30.1 v1(56.56,30.5)
  LYR4 w0.133: 56.56,30.1 56.56,29.17 57.28,28.45 57.28,26.92 58.8,25.4 v1(58.8,19.56)
CVIDEO_DIN11: length 21.7
  TOP w0.121: v1(58.42,13.46) 58.21,13.67 J16.13
  TOP w0.254: v1(56.56,31.3) U7.R18
  LYR4 w0.121: v1(56.56,31.3) 56.56,31.29 56.13,30.86 56.13,30.1
  LYR4 w0.133: v1(58.42,13.46) 58.93,13.97 58.93,17.27 58.36,17.84 58.36,25.46 57.02,26.8 57.02,28.32 56.13,29.21 56.13,30.1
CVIDEO_DIN14_HSYNC: length 16.4
  TOP w0.121: J16.12 57.71,19.25 56.9,20.07 54.36,20.07 53.85,20.57 53.85,23.37 54.58,24.1 54.58,30.88 U7.V19
CVIDEO_DIN15_VSYNC: length 22.2
  TOP w0.121: v1(57.15,13.46) 57.15,15.05 J16.11 ; U7.V18 54.16,31.3 54.16,30.66 53.74,30.25 53.74,27.03 54.26,26.51 54.26,24.29 53.6,23.63 v1(53.6,19.56)
  LYR4 w0.133: v1(53.6,19.56) 53.6,17.01 v1(57.15,13.46)
DDC_SCL: length 34.9
  TOP w0.121: DN2.3 26.4,41.67 24.13,43.94 v1(22.86,43.94) ; v1(24.13,48.26) 24.33,48.46 U16.8
  LYR3 w0.133: v1(22.86,43.94) 21.59,45.21 3.78,45.21 J8.15
  BOTTOM w0.121: v1(24.13,48.26) 23.37,47.5 23.37,44.45 v1(22.86,43.94) 20.83,41.91 20.57,41.91 20.32,41.66 R120.2
DDC_SDA: length 29.9
  TOP w0.121: v1(22.61,41.91) 22.61,40.66 DN1.3 ; v1(24.13,45.73) 24.13,45.72 24.33,45.52 U16.1
  LYR3 w0.121: 3.85,38.61 J8.12
  LYR3 w0.133: 3.85,38.61 4.1,38.86 9.14,38.86 11.18,40.89 21.59,40.89 v1(22.61,41.91)
  BOTTOM w0.121: R121.2 22.35,41.15 22.61,41.4 v1(22.61,41.91) 23.62,42.93 23.62,45.22 v1(24.13,45.73)
DDR_A0: length 18.7
  TOP w0.254: U17.M8 v1(34.96,43.3)
  LYR3 w0.121: v1(34.96,43.3) 35.36,42.9 35.93,42.9
  LYR3 w0.133: v1(49.53,41.66) 48.64,42.55 48.64,44.07 48.51,44.2 45.09,44.2 44.58,43.69 40.77,43.69 40.64,43.81 39.24,43.81 38.33,42.9 35.93,42.9
  BOTTOM w0.121: R230.2 v1(49.53,41.66)
DDR_A1: length 18.6
  TOP w0.254: U17.M3 v1(39.76,43.3)
  LYR3 w0.133: v1(39.76,43.3) 44.82,43.3 45.34,43.81 48.13,43.81 48.26,43.69 48.26,42.16 49.02,41.4 49.02,39.88 49.15,39.75 49.91,39.75 50.04,39.88 50.04,42.58 49.95,42.67 v1(49.53,42.67)
  BOTTOM w0.121: R231.2 v1(49.53,42.67)
DDR_A2: length 18.9
  TOP w0.121: v1(44.2,44.2) 43.81,44.2 43.69,44.32 43.69,46.35 43.81,46.48 45.08,46.48 45.21,46.35 45.21,44.2 46.74,42.67 R232.2
  TOP w0.254: v1(35.76,43.3) U17.M7
  LYR3 w0.133: v1(35.76,43.3) 37.97,43.3 38.99,44.32 40.82,44.32 41.01,44.51 43.89,44.51 v1(44.2,44.2)
DDR_A3: length 19
  TOP w0.121: U17.N2 39.76,44.1 39.09,44.1 38.86,44.32 38.86,46.1 38.99,46.23 41.78,46.23 41.91,46.1 41.91,44.32 42.04,44.2 43.18,44.2 43.31,44.32 43.31,46.74 43.43,46.86 45.43,46.86 45.56,46.74 45.56,44.6 46.47,43.69 R233.2
DDR_A4: length 19
  TOP w0.254: U17.N8 v1(34.96,44.1)
  LYR3 w0.121: v1(34.96,44.1) 34.96,44.1 35.36,44.5 36.07,44.5 36.07,44.51
  LYR3 w0.133: 36.07,44.51 36.58,45.01 36.58,45.97 37.34,46.74 40.89,46.74 41.02,46.86 41.02,47.24 41.15,47.37 43.18,47.37 43.31,47.24 43.31,46.86 43.43,46.74 43.66,46.74 48.51,46.74 v1(49.53,45.72)
  BOTTOM w0.121: R234.2 v1(49.53,45.72)
DDR_A5: length 18.5
  TOP w0.121: U17.N3 38.72,43.7 38.48,43.94 38.48,46.86 38.61,46.99 42.16,46.99 42.29,46.86 42.29,44.83 42.42,44.7 42.8,44.7 42.93,44.83 42.93,47.12 43.05,47.24 45.84,47.24 45.97,47.12 45.97,46.49 46.74,45.72 R235.2
DDR_A6: length 19
  TOP w0.121: R236.2 46.99,44.7 v1(45.97,45.72)
  TOP w0.254: v1(35.76,44.1) U17.N7
  LYR3 w0.133: v1(35.76,44.1) 36.23,44.1 37.08,44.96 37.08,45.94 37.5,46.35 43.5,46.35 43.5,46.35 44.13,46.35 44.13,46.35 48.01,46.35 48.13,46.23 48.13,45.85 48.01,45.72 v1(45.97,45.72)
DDR_A7: length 18.7
  TOP w0.254: v1(40.56,44.9) U17.P2
  LYR3 w0.121: 41.76,44.9 v1(40.56,44.9)
  LYR3 w0.133: 41.76,44.9 48.9,44.9 49.02,44.77 49.02,44.42 49.15,44.3 50.93,44.3 51.05,44.17 51.05,41.53 50.93,41.4 50.67,41.4 50.55,41.53 50.55,43.56 50.42,43.69 v1(49.53,43.69)
  BOTTOM w0.121: R237.2 v1(49.53,43.69)
DDR_A8: length 19
  TOP w0.254: U17.P8 v1(34.96,44.9)
  LYR3 w0.133: v1(49.53,47.75) 48.64,48.64 39.62,48.64 38.86,47.88 36.45,47.88 34.54,45.97 34.54,45.31 v1(34.96,44.9)
  BOTTOM w0.121: R238.2 v1(49.53,47.75)
DDR_A9: length 18.6
  TOP w0.254: U17.P3 v1(39.76,44.9)
  LYR3 w0.121: v1(39.76,44.9) 39.99,44.9 40.39,45.3 41.75,45.3 41.76,45.29
  LYR3 w0.133: v1(49.53,44.7) 51.69,44.7 51.82,44.83 51.82,45.09 51.69,45.21 50.8,45.21 50.67,45.34 50.67,46.48 50.55,46.61 50.29,46.61 50.16,46.48 50.16,45.42 50.04,45.29 41.76,45.29
  BOTTOM w0.121: R239.2 v1(49.53,44.7)
DDR_A10: length 19
  TOP w0.121: U17.M2 39.92,42.9 39.52,42.5 39.45,42.5 39.03,42.5 38.1,43.43 38.1,46.1 37.97,46.23 37.47,46.23 37.34,46.35 37.34,47.24 37.47,47.37 39.5,47.37 39.62,47.5 39.62,48.01 39.75,48.13 46.19,48.13 46.32,48.01 46.32,47.03 46.61,46.74 R240.2
DDR_A11: length 18.8
  TOP w0.254: v1(35.76,44.9) U17.P7
  LYR3 w0.133: v1(35.76,44.9) 35.76,45.92 36.96,47.12 40.51,47.12 40.64,47.24 40.64,47.75 40.77,47.88 43.56,47.88 43.69,47.75 43.69,47.24 43.81,47.12 46.61,47.12 46.74,47.24 v1(46.74,47.75)
  BOTTOM w0.121: R241.2 47.75,48.77 v1(46.74,47.75)
DDR_A12: length 18.7
  TOP w0.121: v1(37.59,45.72) 36.83,45.72 36.7,45.85 36.7,47.62 36.83,47.75 39.12,47.75 39.24,47.88 39.24,48.39 39.37,48.51 47.37,48.51 47.5,48.39 R242.2
  TOP w0.254: v1(40.56,45.7) U17.R2
  LYR3 w0.121: v1(37.59,45.72) 38.01,45.3 39.92,45.3 40.32,45.7 v1(40.56,45.7)
DDR_A13: length 18.9
  TOP w0.254: U17.R8 v1(34.96,45.7)
  LYR3 w0.133: v1(34.96,45.7) 34.96,45.85 36.61,47.5 39.12,47.5 39.88,48.26 44.58,48.26 44.7,48.13 44.7,47.62 44.83,47.5 45.34,47.5 45.47,47.62 45.47,48.13 45.59,48.26 48.01,48.26 v1(49.53,46.74)
  BOTTOM w0.121: R243.2 v1(49.53,46.74)
DDR_BA0: length 19
  TOP w0.121: v1(45.97,42.16) 44.83,42.16 44.7,42.04 44.7,39.5 44.58,39.37 43.56,39.37 43.43,39.5 43.43,42.8 43.31,42.93 41.22,42.93 40.39,42.1 U17.L2
  BOTTOM w0.121: R265.2 47.5,41.27 47.37,41.15 45.54,41.15 45.47,41.07 45.47,40.08 45.39,40.01 45.16,40.01 45.09,40.08 45.09,41.53 45.21,41.66 45.85,41.66 45.97,41.78 v1(45.97,42.16)
DDR_BA1: length 18.5
  TOP w0.121: v1(45.47,43.05) 44.96,43.56 41.4,43.56 40.34,42.5 40.22,42.5 39.99,42.5 39.59,42.1 U17.L3
  BOTTOM w0.121: R266.2 47.5,38.73 47.62,38.61 47.88,38.61 48.01,38.48 48.01,37.72 47.88,37.59 44.83,37.59 44.7,37.72 44.7,42.04 44.83,42.16 45.34,42.16 45.47,42.29 v1(45.47,43.05)
DDR_BA2: length 18.8
  TOP w0.121: v1(46.74,42.16) 46.23,41.66 45.21,41.66 45.09,41.53 45.09,39.04 44.96,38.92 43.05,38.92 42.93,39.04 42.93,41.97 42.8,42.1 U17.L1
  BOTTOM w0.121: v1(46.74,42.16) 46.74,45.59 46.86,45.72 47.37,45.72 47.5,45.59 R267.2
DDR_CASN: length 19
  TOP w0.254: v1(35.76,42.5) U17.L7
  LYR3 w0.133: v1(49.53,39.12) 49.53,38.73 49.4,38.61 48.64,38.61 48.51,38.73 48.51,41.27 47.22,42.57 44.55,42.57 44.23,42.89 39.08,42.89 38.69,42.5 v1(35.76,42.5)
  BOTTOM w0.121: R127.2 v1(49.53,39.12)
DDR_CKE: length 18.9
  TOP w0.121: U17.K2 40.51,41.66 42.16,41.66 42.29,41.53 42.29,35.69 42.42,35.56 42.67,35.56 42.8,35.69 42.8,37.85 42.93,37.97 45.34,37.97 45.47,38.1 45.47,41.02 45.59,41.15 46.48,41.15 46.99,41.66 R130.2
DDR_CLKN: length 19
  TOP w0.095: R132.2 v1(46.74,40.64)
  TOP w0.254: U17.K8 v1(34.96,41.7)
  LYR3 w0.102: v1(46.74,40.64) 46.74,40.49 46.61,40.36 46.33,40.36 45.9,39.93 43.82,39.93 43.31,39.42 42.37,39.42 42.04,39.75 41.2,39.75 40.82,40.13 39.37,40.13 39.24,40.26 39.24,40.89 38.93,41.2 38.35,41.2 38.05,40.89 38.05,40.01 37.92,39.88 37.47,39.88 37.34,40.01 37.34,40.89 37.03,41.2 36.5,41.2 36.2,40.89 36.2,40.26 36.07,40.13 35.47,40.13 35.37,40.24 35.37,41.29 v1(34.96,41.7)
DDR_CLKP: length 18.9
  TOP w0.095: R131.2 v1(46.74,39.62)
  TOP w0.254: U17.J8 v1(34.96,40.9)
  LYR3 w0.102: v1(34.96,40.9) 35.06,40.79 35.06,40.11 35.35,39.83 36.19,39.83 36.5,40.13 36.5,40.77 36.63,40.89 36.91,40.89 37.03,40.77 37.03,39.88 37.34,39.57 38.05,39.57 38.35,39.88 38.35,40.77 38.48,40.89 38.81,40.89 38.94,40.77 38.94,40.13 39.24,39.83 40.69,39.83 41.07,39.45 41.91,39.45 42.24,39.12 43.43,39.12 43.94,39.62 46.02,39.62 46.46,40.06 46.76,40.06 46.86,39.95 46.86,39.75 v1(46.74,39.62)
DDR_CSN: length 19
  TOP w0.121: R126.2 v1(46.74,38.61)
  TOP w0.254: U17.L8 v1(34.96,42.5)
  LYR3 w0.121: v1(34.96,42.5) 35.36,42.1 35.93,42.1
  LYR3 w0.133: v1(46.74,38.61) 47.75,38.61 48.13,38.99 48.13,41.02 47.5,41.66 44.83,41.66 44.07,42.42 39.18,42.42 38.86,42.1 35.93,42.1
